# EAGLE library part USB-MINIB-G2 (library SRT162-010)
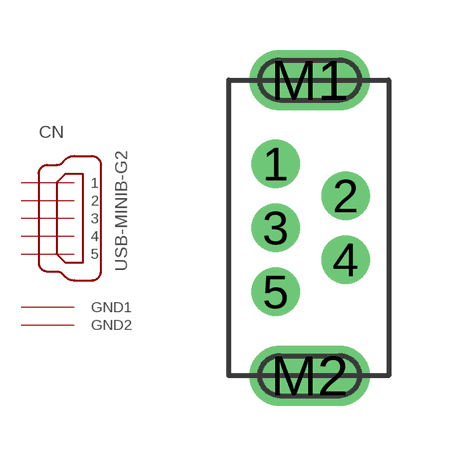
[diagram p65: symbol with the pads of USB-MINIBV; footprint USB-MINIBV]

Designator prefix CN

## USB-MINIB-G2  [USB-MINIBV]
1  1  pas
2  2  pas
3  3  pas
4  4  pas
5  5  pas
M1  GND1  pas
M2  GND2  pas

## Footprint USB-MINIBV (pad centres in mm)
drill 0.7 pad 1.1 round: 1 -0.995,1.6; 2 0.755,0.8; 3 -0.995,0; 4 0.755,-0.8; 5 -0.995,-1.6
drill 1 long: M1 -0.145,3.7; M2 -0.145,-3.7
